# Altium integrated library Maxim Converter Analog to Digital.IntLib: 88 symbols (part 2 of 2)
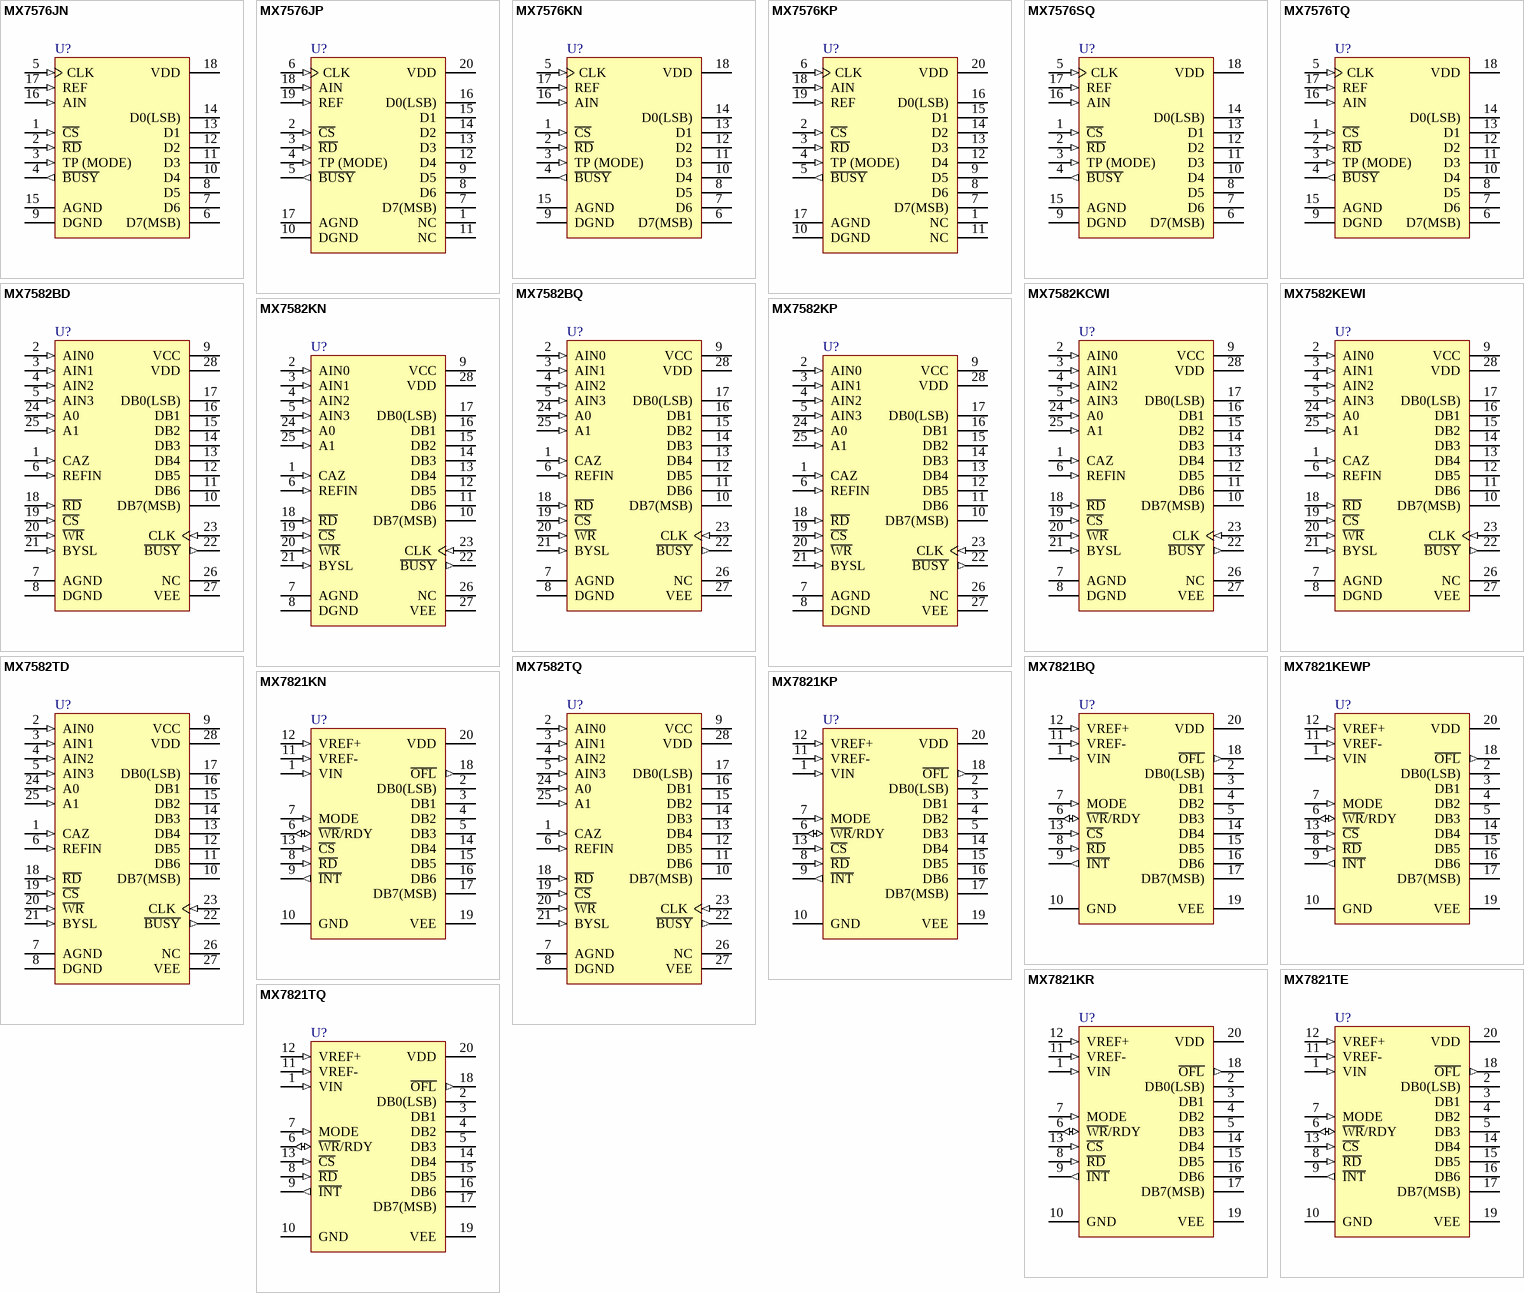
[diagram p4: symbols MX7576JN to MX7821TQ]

## MX7582KEWI
designator U?
Calibrated 4-Channel 12-Bit ADC
footprint WSO28_N (SOIC, 28-Leads, Body 17.9x7.5mm, Pitch 1.27mm, IPC Medium Density)
footprint WSO28_L (SOIC, 28-Leads, Body 17.9x7.5mm, Pitch 1.27mm, IPC High Density)
footprint WSO28_M (SOIC, 28-Leads, Body 17.9x7.5mm, Pitch 1.27mm, IPC Low Density)
3D model WSO28 (28-Pin Small Outline Integrated Circuit 1.27 mm Pitch)
pins: 1 CAZ (in), 2 AIN0 (in), 3 AIN1 (in), 4 AIN2 (in), 5 AIN3 (in), 6 REFIN (in), 7 AGND (power), 8 DGND (power), 9 VCC (power), 10 DB7(MSB) (hiz), 11 DB6 (hiz), 12 DB5 (hiz), 13 DB4 (hiz), 14 DB3 (hiz), 15 DB2 (hiz), 16 DB1 (hiz), 17 DB0(LSB) (hiz), 18 ~{RD} (in), 19 ~{CS} (in), 20 ~{WR} (in), 21 BYSL (in), 22 ~{BUSY} (out), 23 CLK (in), 24 A0 (in), 25 A1 (in), 26 NC, 27 VEE (power), 28 VDD (power)

## MX7582KN
designator U?
Calibrated 4-Channel 12-Bit ADC
footprint NI28A (DIP, 28-Leads, Row Spacing 7.62mm, Pitch 2.54mm, Body 34.8x6.99mm)
3D model NI28 (DIP, 28-Pin, Row Spacing 7.62 mm, Pitch 2.54 mm)
pins: 1 CAZ (in), 2 AIN0 (in), 3 AIN1 (in), 4 AIN2 (in), 5 AIN3 (in), 6 REFIN (in), 7 AGND (power), 8 DGND (power), 9 VCC (power), 10 DB7(MSB) (hiz), 11 DB6 (hiz), 12 DB5 (hiz), 13 DB4 (hiz), 14 DB3 (hiz), 15 DB2 (hiz), 16 DB1 (hiz), 17 DB0(LSB) (hiz), 18 ~{RD} (in), 19 ~{CS} (in), 20 ~{WR} (in), 21 BYSL (in), 22 ~{BUSY} (out), 23 CLK (in), 24 A0 (in), 25 A1 (in), 26 NC, 27 VEE (power), 28 VDD (power)

## MX7582KP
designator U?
Calibrated 4-Channel 12-Bit ADC
footprint PLCC28_N (Leaded Chip Carrier, 28-Leads, Body 11.5x11.5mm, Pitch 1.27mm, IPC Medium Density)
footprint PLCC28_L (Leaded Chip Carrier, 28-Leads, Body 11.5x11.5mm, Pitch 1.27mm, IPC High Density)
footprint PLCC28_M (Leaded Chip Carrier, 28-Leads, Body 11.5x11.5mm, Pitch 1.27mm, IPC Low Density)
3D model MX7582-PLCC28 (28-Pin Leaded Chip Carrier 1.27 mm Pitch)
pins: 1 CAZ (in), 2 AIN0 (in), 3 AIN1 (in), 4 AIN2 (in), 5 AIN3 (in), 6 REFIN (in), 7 AGND (power), 8 DGND (power), 9 VCC (power), 10 DB7(MSB) (hiz), 11 DB6 (hiz), 12 DB5 (hiz), 13 DB4 (hiz), 14 DB3 (hiz), 15 DB2 (hiz), 16 DB1 (hiz), 17 DB0(LSB) (hiz), 18 ~{RD} (in), 19 ~{CS} (in), 20 ~{WR} (in), 21 BYSL (in), 22 ~{BUSY} (out), 23 CLK (in), 24 A0 (in), 25 A1 (in), 26 NC, 27 VEE (power), 28 VDD (power)

## MX7582TD
designator U?
Calibrated 4-Channel 12-Bit ADC
footprint PI28 (DIP, 28-Leads, Row Spacing 15.24mm, Pitch 2.54mm, Body 36.83x13.98mm)
3D model JI28 (DIP, 28-Pin, Row Spacing 15.24 mm, Pitch 2.54 mm)
pins: 1 CAZ (in), 2 AIN0 (in), 3 AIN1 (in), 4 AIN2 (in), 5 AIN3 (in), 6 REFIN (in), 7 AGND (power), 8 DGND (power), 9 VCC (power), 10 DB7(MSB) (hiz), 11 DB6 (hiz), 12 DB5 (hiz), 13 DB4 (hiz), 14 DB3 (hiz), 15 DB2 (hiz), 16 DB1 (hiz), 17 DB0(LSB) (hiz), 18 ~{RD} (in), 19 ~{CS} (in), 20 ~{WR} (in), 21 BYSL (in), 22 ~{BUSY} (out), 23 CLK (in), 24 A0 (in), 25 A1 (in), 26 NC, 27 VEE (power), 28 VDD (power)

## MX7582TQ
designator U?
Calibrated 4-Channel 12-Bit ADC
footprint JI28A (DIP, 28-Leads, Row Spacing 15.24mm, Pitch 2.54mm, Body 37.15x14.1mm)
3D model JI28 (DIP, 28-Pin, Row Spacing 15.24 mm, Pitch 2.54 mm)
pins: 1 CAZ (in), 2 AIN0 (in), 3 AIN1 (in), 4 AIN2 (in), 5 AIN3 (in), 6 REFIN (in), 7 AGND (power), 8 DGND (power), 9 VCC (power), 10 DB7(MSB) (hiz), 11 DB6 (hiz), 12 DB5 (hiz), 13 DB4 (hiz), 14 DB3 (hiz), 15 DB2 (hiz), 16 DB1 (hiz), 17 DB0(LSB) (hiz), 18 ~{RD} (in), 19 ~{CS} (in), 20 ~{WR} (in), 21 BYSL (in), 22 ~{BUSY} (out), 23 CLK (in), 24 A0 (in), 25 A1 (in), 26 NC, 27 VEE (power), 28 VDD (power)

## MX7821BQ
designator U?
660ns µP-Compatible, 8-Bit ADC with Track/Hold
footprint JP20 (DIP, 20-Leads, Row Spacing 7.62mm, Pitch 2.54mm, Body 25.91x6.73mm)
3D model PP20 (DIP, 20-Pin, Row Spacing 7.62 mm, Pitch 2.54 mm)
pins: 1 VIN (in), 2 DB0(LSB) (hiz), 3 DB1 (hiz), 4 DB2 (hiz), 5 DB3 (hiz), 6 ~{WR}/RDY (io), 7 MODE (in), 8 ~{RD} (in), 9 ~{INT} (out), 10 GND (power), 11 VREF- (in), 12 VREF+ (in), 13 ~{CS} (in), 14 DB4 (hiz), 15 DB5 (hiz), 16 DB6 (hiz), 17 DB7(MSB) (hiz), 18 ~{OFL} (out), 19 VEE (power), 20 VDD (power)

## MX7821KEWP
designator U?
660ns µP-Compatible, 8-Bit ADC with Track/Hold
footprint WSO20_N (SOIC, 20-Leads, Body 12.8x7.5mm, Pitch 1.27mm, IPC Medium Density)
footprint WSO20_L (SOIC, 20-Leads, Body 12.8x7.5mm, Pitch 1.27mm, IPC High Density)
footprint WSO20_M (SOIC, 20-Leads, Body 12.8x7.5mm, Pitch 1.27mm, IPC Low Density)
3D model WSO20 (20-Pin Small Outline Integrated Circuit 1.27 mm Pitch)
pins: 1 VIN (in), 2 DB0(LSB) (hiz), 3 DB1 (hiz), 4 DB2 (hiz), 5 DB3 (hiz), 6 ~{WR}/RDY (io), 7 MODE (in), 8 ~{RD} (in), 9 ~{INT} (out), 10 GND (power), 11 VREF- (in), 12 VREF+ (in), 13 ~{CS} (in), 14 DB4 (hiz), 15 DB5 (hiz), 16 DB6 (hiz), 17 DB7(MSB) (hiz), 18 ~{OFL} (out), 19 VEE (power), 20 VDD (power)

## MX7821KN
designator U?
660ns µP-Compatible, 8-Bit ADC with Track/Hold
footprint PP20 (DIP, 20-Leads, Row Spacing 7.62mm, Pitch 2.54mm, Body 26.16x7.24mm)
3D model PP20 (DIP, 20-Pin, Row Spacing 7.62 mm, Pitch 2.54 mm)
pins: 1 VIN (in), 2 DB0(LSB) (hiz), 3 DB1 (hiz), 4 DB2 (hiz), 5 DB3 (hiz), 6 ~{WR}/RDY (io), 7 MODE (in), 8 ~{RD} (in), 9 ~{INT} (out), 10 GND (power), 11 VREF- (in), 12 VREF+ (in), 13 ~{CS} (in), 14 DB4 (hiz), 15 DB5 (hiz), 16 DB6 (hiz), 17 DB7(MSB) (hiz), 18 ~{OFL} (out), 19 VEE (power), 20 VDD (power)

## MX7821KP
designator U?
660ns µP-Compatible, 8-Bit ADC with Track/Hold
footprint PLCC20_N (Leaded Chip Carrier, 20-Leads, Body 9x9mm, Pitch 1.27mm, IPC Medium Density)
footprint PLCC20_L (Leaded Chip Carrier, 20-Leads, Body 9x9mm, Pitch 1.27mm, IPC High Density)
footprint PLCC20_M (Leaded Chip Carrier, 20-Leads, Body 9x9mm, Pitch 1.27mm, IPC Low Density)
3D model MX7821-PLCC20 (20-Pin Leaded Chip Carrier 1.27 mm Pitch)
pins: 1 VIN (in), 2 DB0(LSB) (hiz), 3 DB1 (hiz), 4 DB2 (hiz), 5 DB3 (hiz), 6 ~{WR}/RDY (io), 7 MODE (in), 8 ~{RD} (in), 9 ~{INT} (out), 10 GND (power), 11 VREF- (in), 12 VREF+ (in), 13 ~{CS} (in), 14 DB4 (hiz), 15 DB5 (hiz), 16 DB6 (hiz), 17 DB7(MSB) (hiz), 18 ~{OFL} (out), 19 VEE (power), 20 VDD (power)

## MX7821KR
designator U?
660ns µP-Compatible, 8-Bit ADC with Track/Hold
footprint WSO20_N (SOIC, 20-Leads, Body 12.8x7.5mm, Pitch 1.27mm, IPC Medium Density)
footprint WSO20_L (SOIC, 20-Leads, Body 12.8x7.5mm, Pitch 1.27mm, IPC High Density)
footprint WSO20_M (SOIC, 20-Leads, Body 12.8x7.5mm, Pitch 1.27mm, IPC Low Density)
3D model WSO20 (20-Pin Small Outline Integrated Circuit 1.27 mm Pitch)
pins: 1 VIN (in), 2 DB0(LSB) (hiz), 3 DB1 (hiz), 4 DB2 (hiz), 5 DB3 (hiz), 6 ~{WR}/RDY (io), 7 MODE (in), 8 ~{RD} (in), 9 ~{INT} (out), 10 GND (power), 11 VREF- (in), 12 VREF+ (in), 13 ~{CS} (in), 14 DB4 (hiz), 15 DB5 (hiz), 16 DB6 (hiz), 17 DB7(MSB) (hiz), 18 ~{OFL} (out), 19 VEE (power), 20 VDD (power)

## MX7821TE
designator U?
660ns µP-Compatible, 8-Bit ADC with Track/Hold
footprint LCC20 (Leadless Chip Carrier; 20 Terminals; Body 8.9 x 8.9 mm)
footprint LCC20_N (Leadless Chip Carrier, 20-Leads, Body 8.9x8.9mm, Pitch 1.27mm, IPC Medium Density)
footprint LCC20_L (Leadless Chip Carrier, 20-Leads, Body 8.9x8.9mm, Pitch 1.27mm, IPC High Density)
footprint LCC20_M (Leadless Chip Carrier, 20-Leads, Body 8.9x8.9mm, Pitch 1.27mm, IPC Low Density)
pins: 1 VIN (in), 2 DB0(LSB) (hiz), 3 DB1 (hiz), 4 DB2 (hiz), 5 DB3 (hiz), 6 ~{WR}/RDY (io), 7 MODE (in), 8 ~{RD} (in), 9 ~{INT} (out), 10 GND (power), 11 VREF- (in), 12 VREF+ (in), 13 ~{CS} (in), 14 DB4 (hiz), 15 DB5 (hiz), 16 DB6 (hiz), 17 DB7(MSB) (hiz), 18 ~{OFL} (out), 19 VEE (power), 20 VDD (power)

## MX7821TQ
designator U?
660ns µP-Compatible, 8-Bit ADC with Track/Hold
footprint JP20 (DIP, 20-Leads, Row Spacing 7.62mm, Pitch 2.54mm, Body 25.91x6.73mm)
3D model PP20 (DIP, 20-Pin, Row Spacing 7.62 mm, Pitch 2.54 mm)
pins: 1 VIN (in), 2 DB0(LSB) (hiz), 3 DB1 (hiz), 4 DB2 (hiz), 5 DB3 (hiz), 6 ~{WR}/RDY (io), 7 MODE (in), 8 ~{RD} (in), 9 ~{INT} (out), 10 GND (power), 11 VREF- (in), 12 VREF+ (in), 13 ~{CS} (in), 14 DB4 (hiz), 15 DB5 (hiz), 16 DB6 (hiz), 17 DB7(MSB) (hiz), 18 ~{OFL} (out), 19 VEE (power), 20 VDD (power)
